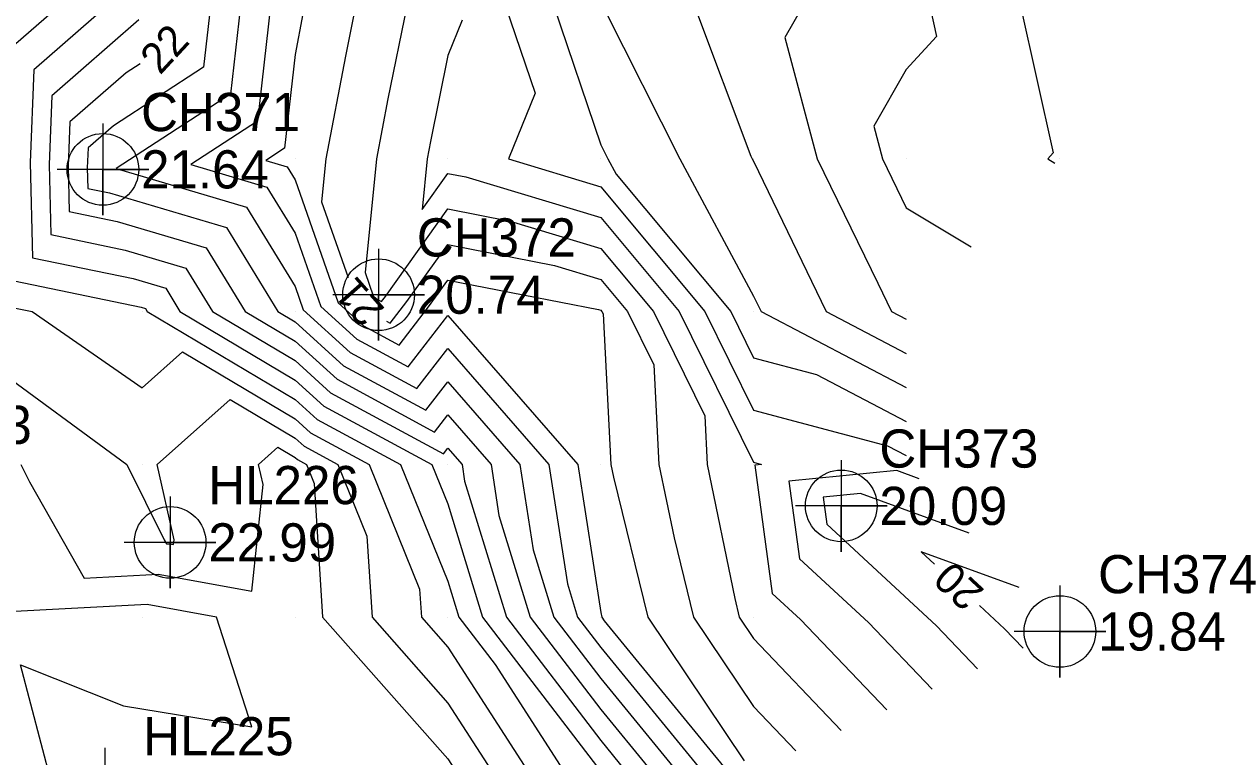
# Model space of a CAD drawing. Extents: x 2531902 to 2533249, y 715219 to 716099.
# Drawn here: x 2532832.3 to 2532911.4, y 715410.9 to 715458.8 of the extents above; entities that cross this region are included whole.
import ezdxf

# ---------------------------------------------------------------- set-up
doc = ezdxf.new("R2010")
doc.units = 0
for name, color, linetype in [('DTM Contours Major', 7, 'Continuous'), ('DTM Contours Major Text', 7, 'Continuous'), ('DTM Contours Minor', 7, 'Continuous'), ('Exist DTM QL2 LIDAR Elevation Point', 7, 'Continuous'), ('Exist DTM Regular Point CELL', 7, 'Continuous'), ('Exist DTM Regular Point Cogo Elevation', 7, 'Continuous'), ('Exist DTM Regular Point Cogo Number', 7, 'Continuous')]:
    doc.layers.add(name, color=color, linetype=linetype)

msp = doc.modelspace()

# ---------------------------------------------------------------- linework, layer by layer
at = {"layer": 'DTM Contours Major'}
for points in [[(2532891.038, 715497.575), (2532891.274, 715490), (2532890.964, 715489.036), (2532890, 715488.635), (2532881.157, 715490), (2532880, 715492.417), (2532879.877, 715490.123), (2532879.803, 715490), (2532877.163, 715482.837), (2532873.006, 715480), (2532872.603, 715477.397), (2532874.358, 715470), (2532873.603, 715466.397), (2532870.165, 715460), (2532870.263, 715459.737), (2532875.19, 715450), (2532880, 715441.02), (2532880.494, 715440), (2532890, 715435.04)], [(2532853.959, 715460), (2532853.291, 715456.709), (2532852.012, 715450), (2532851.729, 715447.187), (2532853.467, 715442.232)], [(2532839.861, 715456.223), (2532838.944, 715455.625), (2532835.265, 715452.415), (2532835.146, 715449.522), (2532835.222, 715446.553), (2532838.364, 715445.902), (2532844.179, 715444.179), (2532846.736, 715440), (2532850, 715438.063), (2532852.744, 715435.576), (2532859.134, 715432.122), (2532860, 715433.238), (2532862.822, 715430), (2532863.338, 715426.662), (2532865.381, 715420), (2532870, 715413.971), (2532873.251, 715410), (2532876.127, 715406.127)], [(2532855.981, 715439.375), (2532856.229, 715439.241), (2532857.324, 715440.654), (2532860, 715444.394), (2532866.973, 715443.027), (2532870, 715442.114), (2532871.764, 715440), (2532873.482, 715436.518), (2532873.817, 715430), (2532874.8, 715425.2), (2532876.074, 715420), (2532880, 715414.161), (2532882.775, 715411.255)], [(2532830, 715436.589), (2532838.988, 715430), (2532841.423, 715425.073), (2532841.577, 715424.802), (2532841.786, 715424.812), (2532842.049, 715424.764), (2532842.081, 715425.065), (2532840.97, 715430), (2532845.757, 715434.243), (2532850, 715431.725), (2532850.587, 715431.193), (2532852.793, 715430), (2532854.699, 715425.301), (2532855.034, 715420), (2532860, 715414.389), (2532862.831, 715410), (2532863.897, 715408.365)], [(2532897.4, 715421.957), (2532890.985, 715424.282), (2532891.847, 715423.485)], [(2532894.784, 715420.77), (2532896.441, 715419.239), (2532897.643, 715417.98)]]:
    msp.add_lwpolyline(points, dxfattribs=at)
at = {"layer": 'DTM Contours Minor'}
for points in [[(2532912.755, 715525.708), (2532910, 715520.525), (2532909.402, 715520.598), (2532909.364, 715520), (2532908.457, 715511.543), (2532908.117, 715510), (2532905.586, 715504.414), (2532900, 715504.511), (2532895.982, 715500), (2532897.911, 715492.089), (2532897.977, 715490), (2532896.036, 715483.964), (2532890, 715481.459), (2532888.274, 715481.726), (2532887.144, 715480), (2532886.294, 715473.706), (2532885.718, 715470), (2532885.195, 715464.805), (2532883.238, 715460), (2532882.059, 715457.941), (2532884.18, 715450), (2532888.133, 715441.867), (2532889.037, 715440), (2532890, 715439.498)], [(2532910, 715478.644), (2532906.892, 715480), (2532900, 715485.872), (2532898.571, 715481.429), (2532895.128, 715480), (2532895.038, 715474.962), (2532894.07, 715470), (2532892.197, 715467.803), (2532891.544, 715460), (2532891.985, 715458.015), (2532890, 715455.853), (2532887.868, 715452.132), (2532888.437, 715450), (2532890, 715446.785), (2532894.245, 715444.245)], [(2532910, 715473.307), (2532904.133, 715475.867), (2532904.015, 715470), (2532900, 715465.054), (2532897.674, 715462.326), (2532897.48, 715460), (2532899.618, 715450.382), (2532899.268, 715450), (2532899.726, 715449.726)], [(2532830, 715469.839), (2532837.687, 715460), (2532832.9, 715455.822), (2532832.65, 715449.754), (2532832.809, 715443.526), (2532839.401, 715442.16), (2532841.529, 715441.529), (2532842.465, 715440), (2532850, 715435.527), (2532851.881, 715433.822), (2532858.953, 715430), (2532860, 715427.418), (2532862.275, 715420), (2532869.728, 715410.272), (2532869.903, 715410), (2532869.957, 715409.918), (2532870, 715409.908), (2532874.222, 715404.222)], [(2532830, 715465.827), (2532834.552, 715460), (2532831.717, 715457.526)], [(2532844.453, 715460), (2532844, 715456), (2532838.107, 715452.159), (2532836.448, 715450.711), (2532836.394, 715449.406), (2532836.428, 715448.067), (2532837.845, 715447.774), (2532845.504, 715445.504), (2532848.872, 715440), (2532850, 715439.33), (2532853.175, 715436.452), (2532858.553, 715433.546), (2532860, 715435.412), (2532864.715, 715430), (2532865.578, 715424.422), (2532866.934, 715420), (2532870, 715415.998), (2532874.91, 715410)], [(2532846.422, 715460), (2532845.768, 715454.232), (2532838.292, 715449.359), (2532846.829, 715446.829), (2532850, 715441.646), (2532850.539, 715440.109), (2532853.607, 715437.329), (2532857.972, 715434.969), (2532860, 715437.585), (2532866.609, 715430), (2532867.818, 715422.182), (2532868.487, 715420), (2532870, 715418.026), (2532876.57, 715410)], [(2532848.39, 715460), (2532847.536, 715452.464), (2532843.184, 715449.627), (2532848.154, 715448.154), (2532850, 715445.137), (2532851.682, 715440.341), (2532854.038, 715438.206), (2532857.391, 715436.393), (2532860, 715439.758), (2532868.502, 715430), (2532870, 715420.318), (2532870.078, 715420), (2532870.238, 715419.762), (2532878.23, 715410)], [(2532857.308, 715460), (2532856.075, 715453.925), (2532855.327, 715450), (2532854.579, 715442.552), (2532855.111, 715441.036), (2532855.332, 715440.835), (2532855.648, 715440.665), (2532855.908, 715441.001), (2532860, 715446.721), (2532864.079, 715445.921), (2532870, 715444.136), (2532873.45, 715440), (2532876.81, 715433.19), (2532876.975, 715430), (2532878.77, 715421.23), (2532879.072, 715420), (2532880, 715418.619), (2532885.748, 715412.6)], [(2532863.775, 715460), (2532865.703, 715454.297), (2532863.958, 715450), (2532870, 715448.178), (2532876.822, 715440), (2532880, 715433.56), (2532888.781, 715431.219), (2532890, 715430.583)], [(2532866.931, 715460), (2532870, 715450.922), (2532870.467, 715450), (2532871.005, 715448.995), (2532878.509, 715440), (2532880, 715436.978), (2532884.121, 715435.879), (2532890, 715432.812)], [(2532876.141, 715460), (2532879.826, 715450.174), (2532879.914, 715450), (2532880, 715449.839), (2532884.766, 715440), (2532890, 715437.269)], [(2532839.781, 715459.092), (2532834.082, 715454.118), (2532833.898, 715449.638), (2532834.015, 715445.039), (2532838.883, 715444.031), (2532842.854, 715442.854), (2532844.6, 715440), (2532850, 715436.795), (2532852.312, 715434.699), (2532859.715, 715430.698), (2532860, 715431.065), (2532860.928, 715430), (2532861.098, 715428.902), (2532863.828, 715420), (2532870, 715411.944), (2532871.591, 715410)], [(2532850.507, 715459.493), (2532850, 715456.833), (2532849.305, 715450.695), (2532848.077, 715449.895), (2532849.479, 715449.479), (2532850, 715448.628), (2532852.825, 715440.573), (2532854.469, 715439.082), (2532856.81, 715437.817), (2532858.741, 715440.308), (2532860, 715442.068), (2532869.867, 715440.133), (2532870, 715440.093), (2532870.077, 715440), (2532870.153, 715439.847), (2532870.66, 715430), (2532870.83, 715429.17), (2532873.076, 715420), (2532879.388, 715410.612)], [(2532860.936, 715459.064), (2532860, 715456.761), (2532858.86, 715451.14), (2532858.642, 715450), (2532858.309, 715446.683), (2532860, 715449.047), (2532861.185, 715448.815), (2532870, 715446.157), (2532875.136, 715440), (2532880, 715430.143), (2532880.536, 715430), (2532880.093, 715429.956), (2532881.231, 715421.563), (2532883.075, 715419.858), (2532888.722, 715413.945)], [(2532831.603, 715442.012), (2532839.92, 715440.288), (2532840.204, 715440.204), (2532840.329, 715440), (2532850, 715434.26), (2532851.45, 715432.946), (2532856.9, 715430), (2532860, 715422.355), (2532860.722, 715420), (2532863.088, 715416.912), (2532867.546, 715410), (2532868.897, 715407.929), (2532870, 715407.673), (2532873.269, 715403.269)], [(2532830.396, 715440.498), (2532832.798, 715440), (2532840, 715435.024), (2532842.638, 715437.362), (2532850, 715432.992), (2532851.018, 715432.069), (2532854.847, 715430), (2532858.153, 715421.847), (2532858.27, 715420), (2532860, 715418.045), (2532865.188, 715410), (2532867.837, 715405.939), (2532870, 715405.438), (2532872.317, 715402.317)], [(2532832.057, 715430), (2532832.614, 715428.873), (2532836.2, 715422.572), (2532841.047, 715422.823), (2532847.159, 715421.702), (2532847.902, 715428.693), (2532847.607, 715430), (2532848.876, 715431.124), (2532850, 715430.457), (2532850.155, 715430.316), (2532850.74, 715430), (2532851.245, 715428.755), (2532851.799, 715420), (2532860, 715410.734), (2532860.473, 715410), (2532865.717, 715401.96), (2532870, 715400.967), (2532870.412, 715400.412)], [(2532890.856, 715429.069), (2532889.379, 715429.605), (2532882.326, 715428.904), (2532883.014, 715423.827), (2532887.53, 715419.651), (2532891.696, 715415.29)], [(2532894.128, 715425.513), (2532887.004, 715428.095), (2532884.558, 715427.851), (2532884.796, 715426.091), (2532891.985, 715419.445), (2532894.669, 715416.635)], [(2532870, 715392.728), (2532867.284, 715395.467), (2532864.831, 715390), (2532862.208, 715387.792), (2532860, 715384.416), (2532857.096, 715390), (2532850, 715397.319), (2532847.644, 715400), (2532847.776, 715407.776), (2532838.579, 715404.928), (2532836.087, 715406.82), (2532834.057, 715409.178), (2532832.037, 715416.892), (2532838.774, 715414.209), (2532847.17, 715412.83), (2532844.853, 715420), (2532840.309, 715420.833), (2532830.823, 715420.341)]]:
    msp.add_lwpolyline(points, dxfattribs=at)
at = {"layer": 'Exist DTM QL2 LIDAR Elevation Point'}
for p, q in [((2532850, 715450), (2532850, 715450)), ((2532860, 715450), (2532860, 715450)), ((2532870, 715450), (2532870, 715450)), ((2532880, 715450), (2532880, 715450)), ((2532890, 715450), (2532890, 715450)), ((2532900, 715450), (2532900, 715450)), ((2532840, 715440), (2532840, 715440)), ((2532850, 715440), (2532850, 715440)), ((2532860, 715440), (2532860, 715440)), ((2532870, 715440), (2532870, 715440)), ((2532880, 715440), (2532880, 715440)), ((2532890, 715440), (2532890, 715440)), ((2532840, 715430), (2532840, 715430)), ((2532850, 715430), (2532850, 715430)), ((2532860, 715430), (2532860, 715430)), ((2532870, 715430), (2532870, 715430)), ((2532880, 715430), (2532880, 715430)), ((2532890, 715430), (2532890, 715430)), ((2532840, 715420), (2532840, 715420)), ((2532850, 715420), (2532850, 715420)), ((2532860, 715420), (2532860, 715420)), ((2532870, 715420), (2532870, 715420)), ((2532880, 715420), (2532880, 715420))]:
    msp.add_line(p, q, dxfattribs=at)
at = {"layer": 'Exist DTM Regular Point CELL'}
for points in [[(2532837.419, 715452.311), (2532837.419, 715446.311), (2532837.419, 715449.311), (2532840.419, 715449.311), (2532834.419, 715449.311)], [(2532855.467, 715444.108), (2532855.467, 715438.108), (2532855.467, 715441.108), (2532858.467, 715441.108), (2532852.467, 715441.108)], [(2532885.743, 715430.293), (2532885.743, 715424.293), (2532885.743, 715427.293), (2532888.743, 715427.293), (2532882.743, 715427.293)], [(2532841.819, 715427.902), (2532841.819, 715421.902), (2532841.819, 715424.902), (2532844.819, 715424.902), (2532838.819, 715424.902)], [(2532900.056, 715422.072), (2532900.056, 715416.072), (2532900.056, 715419.072), (2532903.056, 715419.072), (2532897.056, 715419.072)], [(2532837.558, 715411.468), (2532837.558, 715405.468), (2532837.558, 715408.468), (2532840.558, 715408.468), (2532834.558, 715408.468)]]:
    msp.add_lwpolyline(points, dxfattribs=at)
for centre in [(2532837.419, 715449.311), (2532855.467, 715441.108), (2532885.743, 715427.293), (2532841.819, 715424.902), (2532900.056, 715419.072)]:
    msp.add_circle(centre, 2.344, dxfattribs=at)

# ---------------------------------------------------------------- texts
at = {"layer": 'DTM Contours Major Text'}
for s, rotation, p in [('22', 47.26125, (2532841.165, 715455.439)), ('21', 131.34844, (2532855.933, 715440.168)), ('20', 137.25054, (2532895.191, 715421.756))]:
    msp.add_text(s, height=2, rotation=rotation, dxfattribs=at).set_placement(p)
at = {"layer": 'Exist DTM Regular Point Cogo Elevation'}
for s, p in [('21.64', (2532839.919, 715448.061)), ('20.74', (2532857.967, 715439.858)), ('20.09', (2532888.243, 715426.043)), ('22.99', (2532844.319, 715423.652)), ('19.84', (2532902.556, 715417.822))]:
    msp.add_text(s, height=2.5, dxfattribs=at).set_placement(p)
at = {"layer": 'Exist DTM Regular Point Cogo Number'}
for s, p in [('CH371', (2532839.919, 715451.811)), ('CH372', (2532857.967, 715443.608)), ('HL213', (2532822.915, 715431.344)), ('CH373', (2532888.243, 715429.793)), ('HL226', (2532844.319, 715427.402)), ('CH374', (2532902.556, 715421.572)), ('HL225', (2532840.058, 715410.968))]:
    msp.add_text(s, height=2.5, dxfattribs=at).set_placement(p)

doc.saveas('drawing.dxf')
